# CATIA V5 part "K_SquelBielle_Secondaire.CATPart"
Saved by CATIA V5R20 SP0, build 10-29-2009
Part number: Squelette_bielle_secondaire
Publications: "Plan_bielle_secondaire", "Axe_pivot_1", "Axe_pivot_2", "Droite_bielle_secondaire_1"
Bounding box of the stored display mesh (mm): x -399.988 to 0, y 10 to 50, z 146.894 to 150
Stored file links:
  G:\Khaled_CFAO_2011\ST2M\ST2M_GR2\jcoetard\Khaled\CAD_CATIA\K_SquelBielle_Secondaire.CATPart
  G:\Khaled_CFAO_2011\ST2M\ST2M_GR2\jcoetard\jcoetard\Maquette_jcoetard\Squelette_bielle.CATPart
  G:\Khaled_CFAO_2011\ST2M\ST2M_GR2\jcoetard\jcoetard\Maquette_jcoetard\Squelette_bati.CATPart
  G:\Khaled_CFAO_2011\ST2M\ST2M_GR2\jcoetard\Khaled\CAD_CATIA\K_Squelette.CATProduct
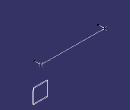
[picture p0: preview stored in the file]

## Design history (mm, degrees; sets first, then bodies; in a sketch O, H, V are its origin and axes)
Set1
  Point1: linked copy from another document
  Point2: linked copy from another document
  Plane1 "Plan_Ref": linked copy from another document
Set2 "Set géométrique"
  Plane2 "Plan_bielle_secondaire": type Offset, RefPlane Plane1, Offset 5, reversed
  Line1 "Axe_pivot_1": type Normal, RefPoint Point1, RefSkin Plane2, Start 0, End 40
  Line2 "Axe_pivot_2": type Normal, RefPoint Point2, RefSkin Plane2, Start 0, End 40
  Line3 "Droite_bielle_secondaire_1": type PtPt, FirstPoint Point1, SecondPoint Point2
Body1 (main body)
